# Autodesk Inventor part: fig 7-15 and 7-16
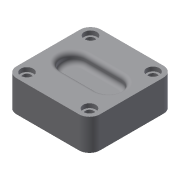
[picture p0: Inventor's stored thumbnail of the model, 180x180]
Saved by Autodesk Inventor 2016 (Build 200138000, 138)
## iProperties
Shininess: 77.0
Angle Display Precision: 2
Document Length Units: 11269
Document Angle Units: 11279
Document Time Units: 11290
Document Mass Units: 11283
Document Length Units Precision: 3
Document Angle Units Precision: 2
Created: 2001-12
Part Number: fig 7-15 and 7-16
Document SubType Name: Modeling
Designer: Renu Muthoo
Density: 1 g/cm^3
Material: Generic
Appearance: Default
Density: 0.0
Volumn: 0.0
Area: 0.0
PropertySet Name: Model Information
Control State: 0
Master: False
Checked Out: False
Author: Renu Muthoo
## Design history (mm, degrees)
sketch "Sketch1"
  geometry: L1 (-20, 20)-(20, 20); L2 (20, 20)-(20, -20.5); L3 (20, -20.5)-(-20, -20.5); L4 (-20, -20.5)-(-20, 20); 1 further point
  constraints: 8 end point, 2 parallel, 1 horizontal, 1 perpendicular, 1 other
  dimensions: "d0" = 40 distance of L1.start L1.end; "d1" = 40.5 distance of L3.end L1.start; "d100" = 20 distance from line of L4 point (0, 0); "d101" = 20 distance from line of L1 point (0, 0)
extrude "Extrusion1" new body sketch "Sketch1" distance "d2" = 15; taper "d3" = 0 deg
workplane "Work Plane1"
workplane "Work Plane2"
workplane "Work Plane3"
workplane "Work Plane4"
fillet "Fillet1" dims "d32" = 5
hole "Hole3" diameter "d66" = 4; stored, may be unused: countersink angle "d70" = 90 deg, drill point angle "d72" = 118 deg; dims "d64" = 10, "d65" = 10, "d67" = 6, "d68" = 6, "d69" = 2, "d71" = 8
hole "Hole4" diameter "d75" = 4; stored, may be unused: countersink angle "d79" = 90 deg, drill point angle "d81" = 118 deg; dims "d73" = 10, "d74" = 10, "d76" = 6, "d77" = 6, "d78" = 2, "d80" = 8
hole "Hole5" diameter "d84" = 4; stored, may be unused: countersink angle "d88" = 90 deg, drill point angle "d90" = 118 deg; dims "d82" = 10, "d83" = 10, "d85" = 6, "d86" = 6, "d87" = 2, "d89" = 8
hole "Hole6" diameter "d93" = 4; stored, may be unused: countersink angle "d97" = 90 deg, drill point angle "d99" = 118 deg; dims "d91" = 10, "d92" = 10, "d94" = 6, "d95" = 6, "d96" = 2, "d98" = 8
fillet "Fillet2" dims "d61" = 2
body "Solid1"
sketch "Sketch8"
  geometry: L1 (-9.844, 1.64)-(1.983, -10.187); L2 (10.469, -1.701)-(-1.358, 10.126); A1 r 6 centre (-5.601, 5.883) between (-1.358, 10.126) and (-9.844, 1.64); A2 r 6 centre (6.226, -5.944) between (1.983, -10.187) and (10.469, -1.701)
  constraints: 4 end point, 4 point on circle, 4 tangent, 2 centre point, 1 parallel
  dimensions: "d29" = 6 radius of A2
extrude "Extrusion2" cut sketch "Sketch8" distance "d30" = 5; taper "d31" = 0 deg
